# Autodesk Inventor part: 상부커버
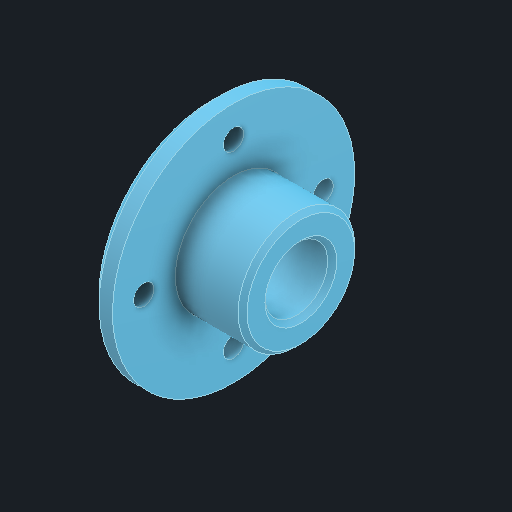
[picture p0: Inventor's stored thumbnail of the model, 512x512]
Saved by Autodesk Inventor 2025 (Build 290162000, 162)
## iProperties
Created: 2025-08
Part Number: 상부커버
Material: 알루미늄 6061
Document SubType Name: Modeling
Designer: infra027
Density: 2.71 g/cm^3
Appearance: 기본값
Author: jhkim
Sending System: Autodesk Inventor 2026
Preprocessor: ST-DEVELOPER v20.1
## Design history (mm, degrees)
feature "솔리드1"
node "솔리드2"
